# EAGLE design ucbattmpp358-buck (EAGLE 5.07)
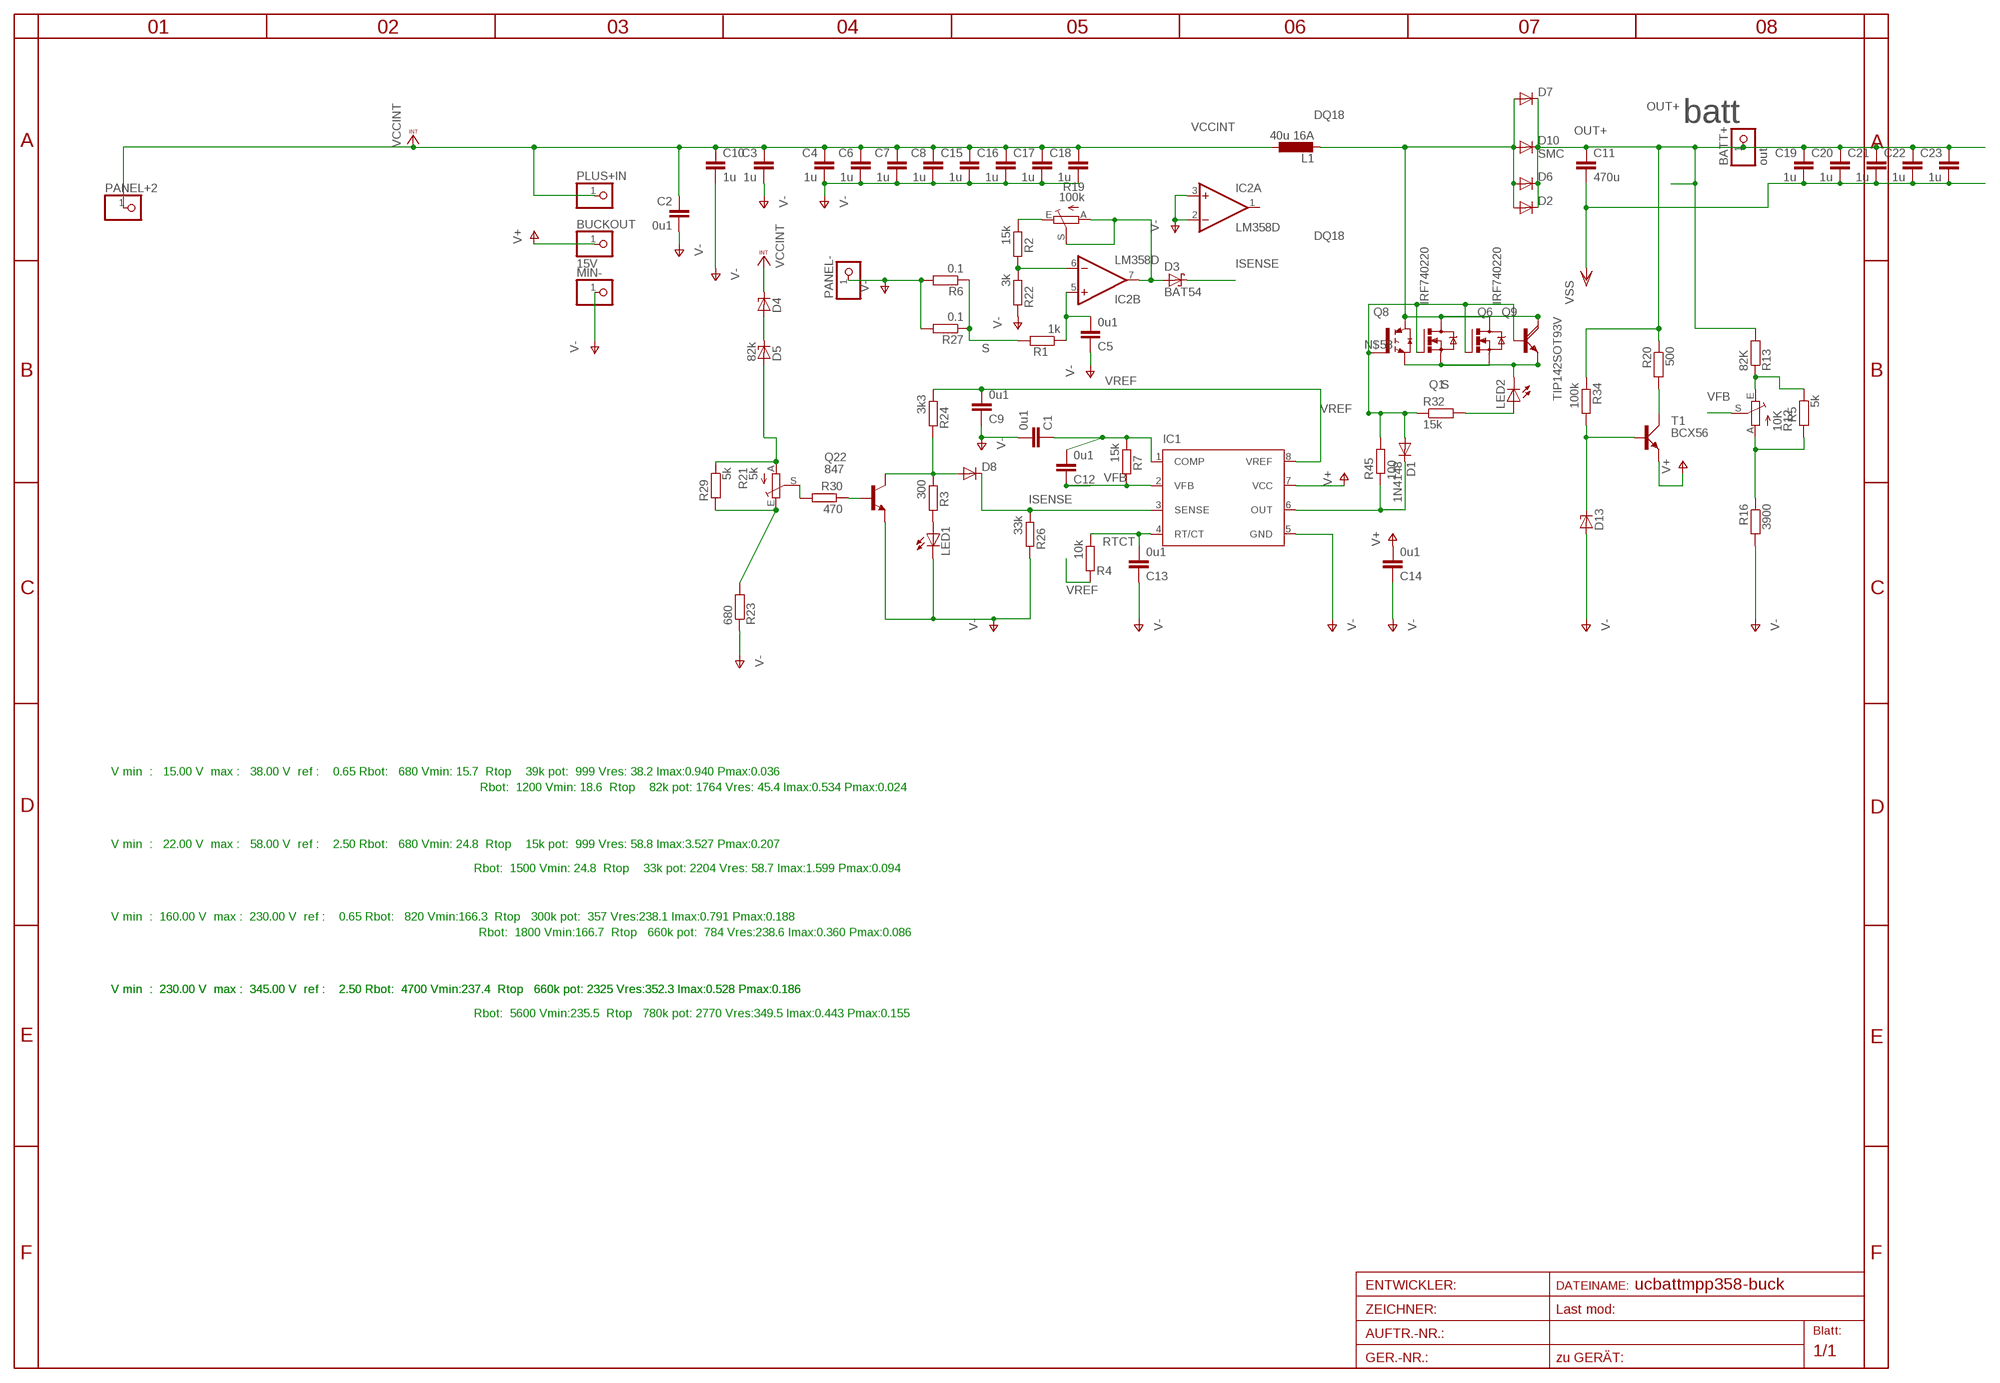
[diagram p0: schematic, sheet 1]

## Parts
BATT+  out  PINHD-1X12MM3  [1X2MM3]
BUCKOUT  15V  PINHD-1X11MM0  [1X1MM0]
C1  0u1  C-EUC1206  [C1206]
C2  0u1  C-EUC1206  [C1206]
C3  1u  C-EUC1206  [C1206]
C4  1u  C-EUC1206  [C1206]
C5  0u1  C-EUC0805  [C0805]
C6  1u  C-EUC1206  [C1206]
C7  1u  C-EUC1206  [C1206]
C8  1u  C-EUC1206  [C1206]
C9  0u1  C-EUC1206  [C1206]
C10  1u  C-EU075-052X106  [C075-052X106]
C11  470u  C-EU075-052X106  [C075-052X106]
C12  0u1  C-EUC0805  [C0805]
C13  0u1  C-EUC1206  [C1206]
C14  0u1  C-EUC1206  [C1206]
C15  1u  C-EUC1206  [C1206]
C16  1u  C-EUC1206  [C1206]
C17  1u  C-EUC1206  [C1206]
C18  1u  C-EUC1206  [C1206]
C19  1u  C-EUC1206  [C1206]
C20  1u  C-EUC1206  [C1206]
C21  1u  C-EUC1206  [C1206]
C22  1u  C-EUC1206  [C1206]
C23  1u  C-EUC1206  [C1206]
D1  1N4148  DIODE-MINIMELF  [MINIMELF]
D2  DIODE-SMC  [SMC]
D3  BAT54  [SOT23]
D4  ZENER-DIODESOD80C  [SOD80C]
D5  82k  ZENER-DIODESOD80C  [SOD80C]
D6  DIODE-SMC  [SMC]
D7  DIODE-SMC  [SMC]
D8  DIODE-MINIMELF  [MINIMELF]
D10  SMC  DIODE-SMC  [SMC]
D13  ZENER-DIODESOD80C  [SOD80C]
IC1  UC1843D8  [SO-08]
IC2  LM358D  [SO08]
L1  40u 16A  L-EU  [RING]
LED1  LEDCHIPLED_1206  [CHIPLED_1206]
LED2  LEDCHIPLED_1206  [CHIPLED_1206]
MIN-  PINHD-1X11MM0  [1X1MM0]
PANEL+2  PINHD-1X12MM3  [1X2MM3]
PANEL-  PINHD-1X12MM3  [1X2MM3]
PLUS+IN  PINHD-1X11MM0  [1X1MM0]
Q1  IRF740220  [TO220BV]
Q6  IRF740220  [TO220BV]
Q8  IRG4BC15UD-S  [D2PACK]
Q9  TIP142SOT93V  [SOT93V]
Q22  847  BC847ASMD  [SOT23]
R1  1k  R-EU_R0805  [R0805]
R2  15k  R-EU_R0805  [R0805]
R3  300  R-EU_R0805  [R0805]
R4  10k  R-EU_R0805  [R0805]
R5  5k  R-EU_R0805  [R0805]
R6  0.1  R-EU_0207/10  [0207/10]
R7  15k  R-EU_R0805  [R0805]
R12  10K  TRIM_EU-S64W  [S64W]
R13  82K  R-EU_R0805  [R0805]
R16  3900  R-EU_R0805  [R0805]
R19  100k  TRIM_EU-S64W  [S64W]
R20  500  R-EU_0204/3  [0204/3]
R21  5k  TRIM_EU-S64W  [S64W]
R22  3k  R-EU_R0805  [R0805]
R23  680  R-EU_R0805  [R0805]
R24  3k3  R-EU_R0805  [R0805]
R26  33k  R-EU_R0805  [R0805]
R27  0.1  R-EU_R3216  [R3216]
R29  5k  R-EU_R0805  [R0805]
R30  470  R-EU_R0805  [R0805]
R32  15k  R-EU_R0805  [R0805]
R34  100k  R-EU_R0805  [R0805]
R45  100  R-EU_R0805  [R0805]
T1  BCX56  [SOT223]

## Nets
DQ18: D2.A D6.A D7.A D10.A L1.2 Q1.D Q6.D Q8.2(C) Q9.C
ISENSE: D3.3(C) D8.C IC1.3(SENSE) R26.1
N$1: C5.2 IC2.5(B:+IN) R1.1
N$2: R2.1 R19.E
N$3: Q22.1(B) R30.1
N$4: LED1.A R3.2
N$5: LED2.A R32.2
N$18: C1.1 C12.2 IC1.1(COMP) R7.1
N$21: R5.2 R12.A R16.1
N$22: D3.1(A) IC2.7(B:OUT) R19.A R19.S
N$23: R20.2 T1.2(C)
N$25: D1.C IC1.6(OUT) R45.1
N$26: D13.C R34.2 T1.1(B)
N$27: IC2.6(B:-IN) R2.2 R22.1
N$30: D4.A D5.C
N$32: D5.A R21.A R29.1
N$34: R21.E R23.2 R29.2
N$37: R5.1 R12.E R13.1
N$58: D1.A Q1.G Q6.G Q8.1(G) Q9.B R32.1 R45.2
N$71: D8.A Q22.3(C) R3.1 R24.2
OUT+: BATT+.1 C11.1 C19.1 C20.1 C21.1 C22.1 C23.1 D2.C D6.C D7.C D10.C R13.2 R20.1 R34.1
PRB1: R21.S R30.2
RTCT: C13.2 IC1.4(RT/CT) R4.1
S: LED2.C Q1.S Q6.S Q8.3(E) Q9.E R1.2 R6.1 R27.1
V+: BUCKOUT.1 C14.2 IC1.7(VCC) T1.3(E)
V-: C1.2 C2.2 C3.2 C4.2 C5.1 C6.2 C7.2 C8.2 C9.1 C10.2 C11.2 C13.1 C14.1 C15.2 C16.2 C17.2 C18.2 C19.2 C20.2 C21.2 C22.2 C23.2 D13.A IC1.5(GND) IC2.2(A:-IN) IC2.3(A:+IN) LED1.C MIN-.1 PANEL-.1 Q22.2(E) R6.2 R16.2 R22.2 R23.1 R26.2 R27.2 ; supply symbol labelled VSS
VCCINT: C2.1 C3.1 C4.1 C6.1 C7.1 C8.1 C10.1 C15.1 C16.1 C17.1 C18.1 D4.C L1.1 PANEL+2.1 PLUS+IN.1
VFB: C12.1 IC1.2(VFB) R7.2 R12.S
VREF: C9.2 IC1.8(VREF) R4.2 R24.1
Unconnected: IC2.1(A:OUT)

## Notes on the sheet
- batt
- V min  :   15.00 V  max :   38.00 V  ref :    0.65 Rbot:   680 Vmin: 15.7  Rtop    39k pot:  999 Vres: 38.2 Imax:0.940 Pmax:0.036
- Rbot:  1200 Vmin: 18.6  Rtop    82k pot: 1764 Vres: 45.4 Imax:0.534 Pmax:0.024
- V min  :   22.00 V  max :   58.00 V  ref :    2.50 Rbot:   680 Vmin: 24.8  Rtop    15k pot:  999 Vres: 58.8 Imax:3.527 Pmax:0.207
- Rbot:  1500 Vmin: 24.8  Rtop    33k pot: 2204 Vres: 58.7 Imax:1.599 Pmax:0.094
- V min  :  160.00 V  max :  230.00 V  ref :    0.65 Rbot:   820 Vmin:166.3  Rtop   300k pot:  357 Vres:238.1 Imax:0.791 Pmax:0.188
- Rbot:  1800 Vmin:166.7  Rtop   660k pot:  784 Vres:238.6 Imax:0.360 Pmax:0.086
- V min  :  230.00 V  max :  345.00 V  ref :    2.50 Rbot:  4700 Vmin:237.4  Rtop   660k pot: 2325 Vres:352.3 Imax:0.528 Pmax:0.186 | V min  :  230.00 V  max :  345.00 V  ref :    2.50 Rbot:  4700 Vmin:237.4  Rtop   660k pot: 2325 Vres:352.3 Imax:0.528 Pmax:0.186
- Rbot:  5600 Vmin:235.5  Rtop   780k pot: 2770 Vres:349.5 Imax:0.443 Pmax:0.155

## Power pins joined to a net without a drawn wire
V+: IC2.8(P:V+)
V-: IC2.4(P:V-)

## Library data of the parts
BATT+ BUCKOUT MIN- PANEL+2 PANEL- PLUS+IN = pinhead:PINHD-1X1: PIN HEADER
C1-C23 = rcl:C-EU: CAPACITOR, European symbol
D1 D2 D6-D8 D10 = diode:DIODE-: DIODE
D3 = diode:BAT54: Schottky Diodes
D4 D5 D13 = diode:ZENER-DIODE: Z-Diode
IC1 = texas:UC1843D8: PULSE WIDTH MODULATOR
IC2 = linear:LM358: OP AMP also LM158; LM258; LM2904 Source: http://cache.national.com/ds/LM/LM158.pdf
L1 = rcl:L-EU: INDUCTOR, European symbol
LED1 LED2 = led:LED: LED
Q1 Q6 = transistor-power:IRF740: N-CHANNEL MOS FET
Q8 = transistor-power:IRG4BC15UD-: INSULATED GATE BIPOLAR TRANSISTOR WITH ULTRAFAST SOFT RECOVERY DIODE
Q9 = transistor-power:TIP142: NPN DARLINGTON TRANSISTOR
Q22 = transistor-npn:BC847*: NPN Transistor
R1-R7 R13 R16 R20 R22-R24 R26 R27 R29 R30 R34 = rcl:R-EU_: RESISTOR, European symbol
R12 R19 R21 = pot:TRIM_EU-: POTENTIOMETER
R32 R45 = rcl-2:R-EU_: RESISTOR, European symbol
T1 = transistor-power:BCX56

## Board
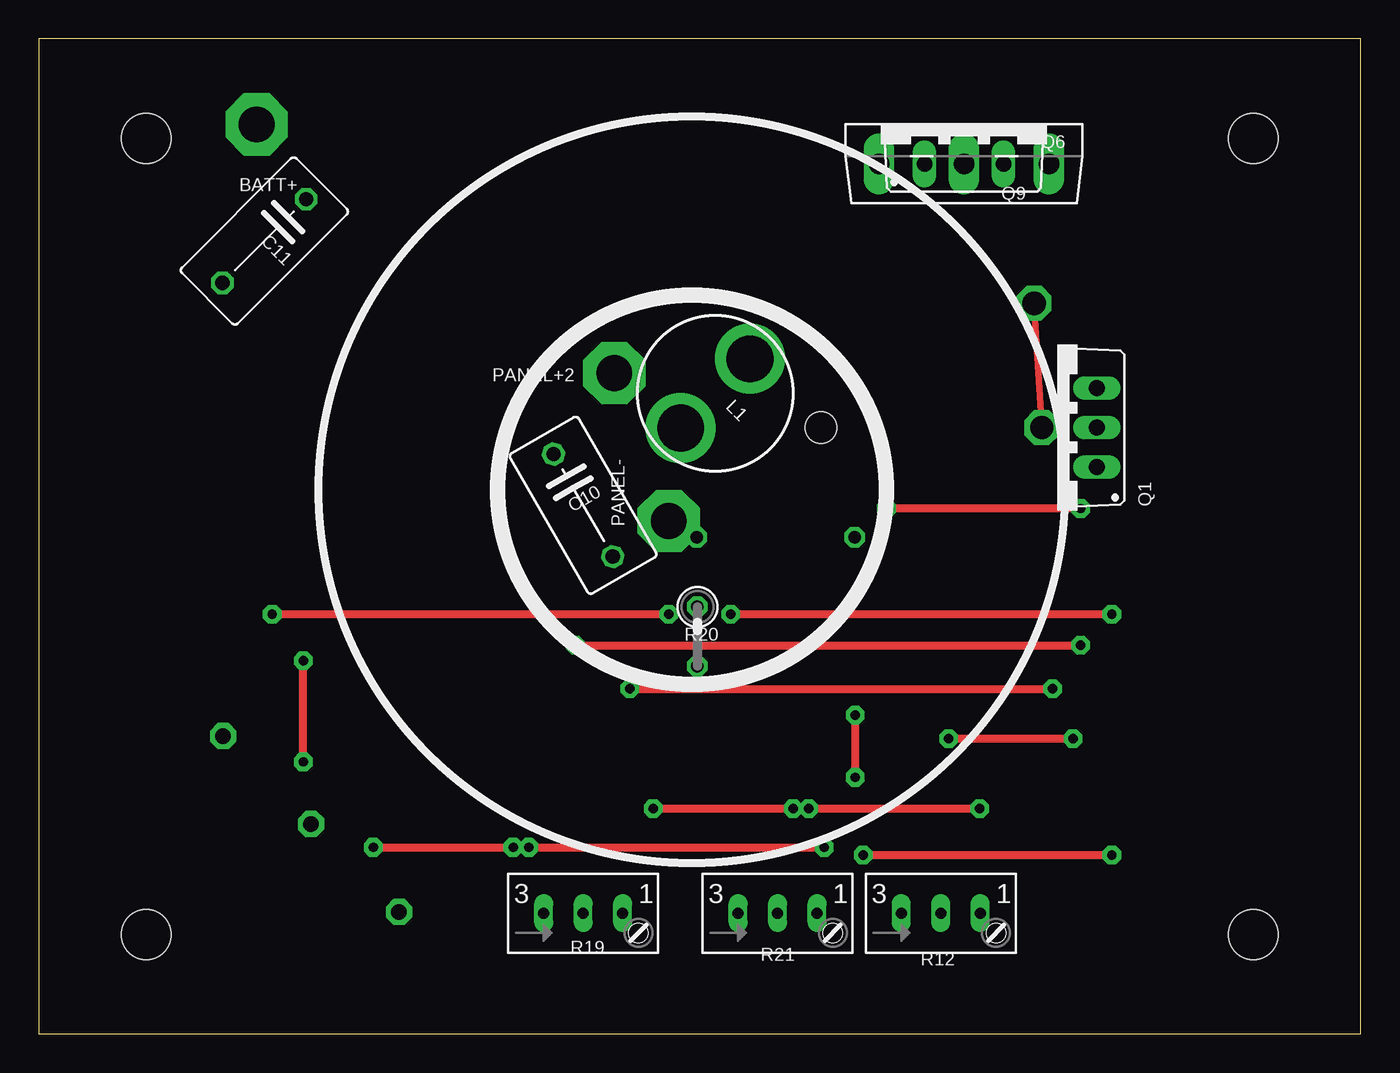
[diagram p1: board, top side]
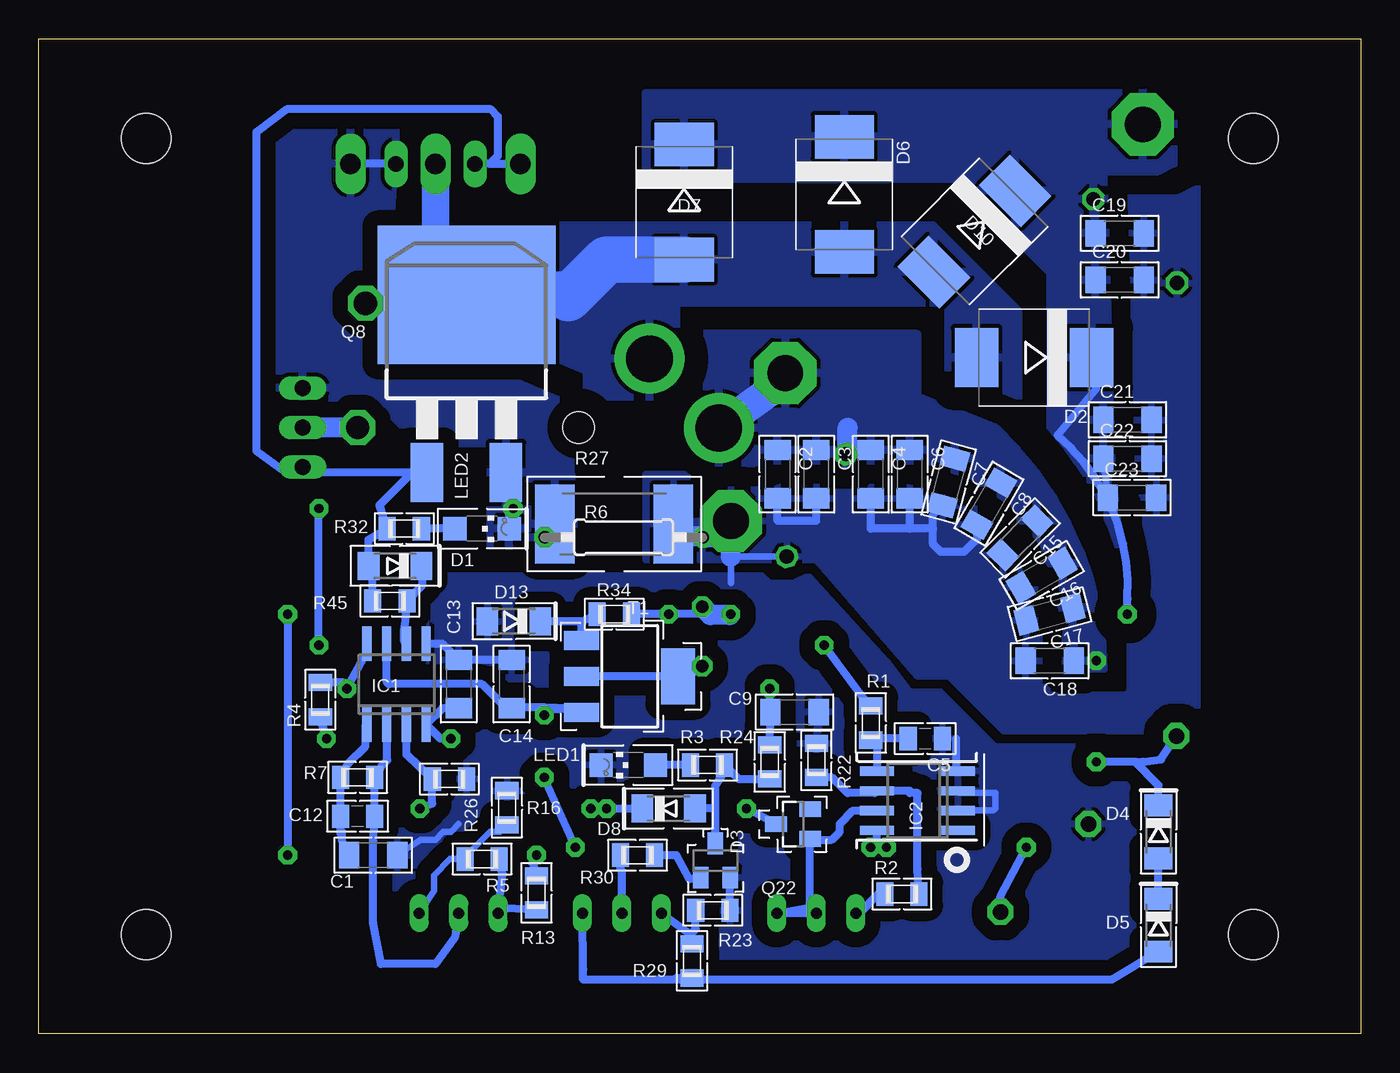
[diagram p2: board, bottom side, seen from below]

Size 85 x 64 mm. Coordinates in mm from the lower left corner, seen from the top.
Outline: 0,0 85,0 85,64 0,64 0,0
Copper layers (1*16): Top 0.035mm / dielectric 1.5mm / Bottom 0.035mm
Design rules "default *": minimum track width 10mil, minimum drill 24mil, track to track 8mil, track to pad 8mil, pad to pad 8mil, via to via 8mil, smd to smd 8mil, copper to edge 1mm, drill to drill 8mil, minimum pad ring 10mil, minimum via ring 8mil, stop-mask expansion 4mil, vias tented up to drill 0mil, thermal gap 10mil
Holes 3.2 mm at 6.9,57.6 6.9,6.4 78.1,6.4 78.1,57.6
Holes 2 mm at 50.3,39

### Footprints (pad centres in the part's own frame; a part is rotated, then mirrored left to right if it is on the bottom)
1X2MM3 = drill 2.3 pad 4 octagon: 1 0,0
1X1MM0 = drill 1 pad 1.676 octagon: 1 0,0
C1206 = smd 1.3 x 1.7: 1 -1.55,0; 2 1.55,0
C0805 = smd 1.1 x 1.5: 1 -1.1,0; 2 1.1,0
C075-052X106 = drill 0.914 octagon: 1 -3.81,0; 2 3.81,0
MINIMELF = smd 1.4 x 1.8: A 1.7,0; C -1.7,0
SMC = smd 2.8 x 3.8: A 3.7,0; C -3.7,0
SOT23 = smd 1 x 1.4: 1 -0.95,-1.1; 2 0.95,-1.1; 3 0,1.1
SOD80C = smd 1.4 x 1.8: A 1.7,0; C -1.7,0
SO-08 = smd 0.6 x 2.2: 1 -1.905,-2.6; 2 -0.635,-2.6; 3 0.635,-2.6; 4 1.905,-2.6; 5 1.905,2.6; 6 0.635,2.6; 7 -0.635,2.6; 8 -1.905,2.6
SO08 = smd 0.6 x 2.2: 1 -1.905,-2.6; 2 -0.635,-2.6; 3 0.635,-2.6; 4 1.905,-2.6; 5 1.905,2.6; 6 0.635,2.6; 7 -0.635,2.6; 8 -1.905,2.6
RING = drill 3 pad 4 round: 1 -3.15,0; 2 3.15,0
CHIPLED_1206 = smd 1.5 x 1.5: A 0,-1.75; C 0,1.75
TO220BV = drill 1.016 long: D 0,-2.54; G -2.54,-2.54; S 2.54,-2.54
D2PACK = smd 2.083 x 3.81: 1 -2.54,-8.89; 3 2.54,-8.89 | smd 11.43 x 8.89: 2 0,2.54
SOT93V = drill 1.3 pad 1.676 long: B -5.461,-2.54; C 0,-2.54; E 5.461,-2.54
R0805 = smd 1.1 x 1.5: 1 -1.1,0; 2 1.1,0
0207/10 = drill 0.813 octagon: 1 -5.08,0; 2 5.08,0
S64W = drill 0.7 long: A 2.54,1.27; E -2.54,1.27; S 0,1.27
0204/3 = drill 0.813 octagon: 1 -1.27,0; 2 2.54,0
R3216 = smd 2.54 x 5.08: 1 -3.81,0; 2 3.81,0
SOT223 = smd 1.219 x 2.235: 1 -2.311,-3.099; 2 0,-3.099; 3 2.311,-3.099 | smd 3.6 x 2.2: 4 0,3.099

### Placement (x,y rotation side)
BATT+  14,58.5 0 top
BUCKOUT  23.16,7.84 90 top
C1  63.5,11.5 0 bottom
C2  37.5,36 270 bottom
C3  35,36 270 bottom
C4  31.5,36 270 bottom
C5  28,19 180 bottom
C6  29,36 270 bottom
C7  26.5,35.5 255 bottom
C8  23.9,34.1 240 bottom
C9  36.4,20.7 180 bottom
C10  35,34 300 top
C11  14.5,51 225 top
C12  64.5,14 180 bottom
C13  58,22.5 270 bottom
C14  54.6,22.5 270 bottom
C15  21.9,31.9 225 bottom
C16  20.5,29.5 210 bottom
C17  20,27 195 bottom
C18  20,24 180 bottom
C19  15.5,51.5 0 bottom
C20  15.5,48.5 0 bottom
C21  15,39.5 0 bottom
C22  15,37 0 bottom
C23  14.7,34.5 0 bottom
D1  62.1,30.1 180 bottom
D2  21,43.5 180 bottom
D3  36.5,13.5 90 bottom
D4  13,13 270 bottom
D5  13,7 270 bottom
D6  33.2,54 270 bottom
D7  43.5,53.5 270 bottom
D8  44.5,14.5 0 bottom
D10  24.83,51.61 225 bottom
D13  54.46,26.55 180 bottom
IC1  62,22.5 0 bottom
IC2  28.5,15 90 bottom
L1  43.5,41.2 45 top
LED1  47.1,17.3 90 bottom
LED2  56.5,32.5 270 bottom
MIN-  17.5,13.5 315.7 top
PANEL+2  37,42.5 0 top
PANEL-  40.5,33 90 top
PLUS+IN  11.84,19.16 90 top
Q1  65.5,39 90 top
Q6  59.5,58.5 0 top
Q8  57.5,45 0 bottom
Q9  59.5,58.5 0 top
Q22  41.49,11.16 0 bottom
R1  31.5,20 90 bottom
R2  29.5,9 0 bottom
R3  42,17.3 180 bottom
R4  66.9,21.5 90 bottom
R5  56.5,11.25 180 bottom
R6  47.4,31.95 0 bottom
R7  64.5,16.5 0 bottom
R12  58,6.5 0 top
R13  53,9.08 90 bottom
R16  54.9,14.55 90 bottom
R19  35,6.5 0 top
R20  42.35,26.2 270 top
R21  47.5,6.5 0 top
R22  35,17.6 90 bottom
R23  41.66,7.96 180 bottom
R24  38,17.5 270 bottom
R26  58.6,16.4 0 bottom
R27  48,32.8 0 bottom
R29  43,4.7 90 bottom
R30  46.5,11.5 180 bottom
R32  61.5,32.5 0 bottom
R34  48,27 180 bottom
R45  62.43,27.85 180 bottom
T1  47,23 270 bottom

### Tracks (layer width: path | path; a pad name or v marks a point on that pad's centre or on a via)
DQ18  (via drill 1.5 pad 1.6, 1.5 pad 1.78)
  Top 0.406: v64,47 v64.5,39
  Bottom 0.406: v64,47 58.9,47 58.9,47.89
  Bottom 1.27: v64.5,39 Q1.D
  Bottom 1.778: 59.5,48.04 Q9.C
  Bottom 2.54: Q8.2 58.9,47.89 59.5,48.04
  Bottom 3: Q8.2 51.04,47.54 50.97,47.34 48.51,49.8 D7.A
  pour Bottom (isolate 1.5, rank 2): 27.5,52 53,52 52,43 49.5,41 44.5,41 44.5,45.5 27.5,45.5 27.5,40.5 22,40.5 22,46.5
ISENSE  (via drill 0.6 pad 1.2)
  Top 0.5: v49.5,14.5 v60.5,14.5 | v39.5,14.5 v48.5,14.5
  Bottom 0.5: IC1.3 61.37,17.96 R26.1 59.7,14.8 v60.5,14.5 | v49.5,14.5 v48.5,14.5 D8.C | D3.3 v39.5,14.5
N$1
  Bottom 0.5: IC2.5 31.1,18.5 R1.1 31.5,19 C5.2
N$2
  Bottom 0.5: R2.1 31,9 32.23,7.77 R19.E
N$3
  Bottom 0.5: Q22.1 43.16,9.96 44,11.5 R30.1
N$4
  Bottom 0.5: R3.2 LED1.A
N$5
  Bottom 0.5: LED2.A R32.2
N$18
  Bottom 0.5: C1.1 65.5,12.45 65.5,13 65.6,12.9 C12.2 R7.1 65.1,17.4 64,18.5 64,19.8 IC1.1
N$21
  Bottom 0.406: R16.1 55.35,13 56,13 57.6,11.4 R5.2 58.55,11.25 59.6,10.2 59.6,9.22 R12.A
N$22
  Bottom 0.5: IC2.7 32.63,14.37 33.5,13.5 33.5,13 34,12.5 35.35,12.5 D3.1 35.4,8.13 R19.A R19.S
N$23
  Bottom 0.5: R20.2 43.19,23 43.5,22 44,22.5 44,23 T1.2
N$25
  Bottom 0.5: IC1.6 61.5,25.23 61.5,26 61.43,26.57 R45.1 60.33,28.87 D1.C
N$26
  Bottom 0.5: R34.2 50.21,26.5 49.99,26.52 | 49.99,26.52 D13.C | T1.1 50.1,26.42 49.99,26.52
N$27
  Bottom 0.5: R2.2 28.5,10.6 28.5,15.5 29,15.5 29,15.63 IC2.6 31.23,15.5 33,15.5 34,16.5 R22.1
N$30
  Bottom 0.5: D5.C D4.A
N$32
  Bottom 0.5: D5.A 16,3.5 44,3.5 | 44,3.5 50,3.5 50,4.14 R21.A | R29.1 44,3.6 44,3.5
N$34
  Bottom 0.5: R29.2 43,6.3 43.1,6.4 | 43.1,6.4 R21.E | R23.2 42.76,6.74 43.1,6.4
N$37
  Bottom 0.5: R13.1 55.03,8.07 R12.E 55.16,10.27 R5.1
N$58
  Bottom 0.406: Q1.G 68.5,36.46 68.5,36.11
  Bottom 0.5: 56,55.96 Q9.B | 56,55.96 Q6.G | R45.2 63.53,29.43 D1.A 63.8,31.8 R32.1 63.1,34.01 61,36.11 | 61,36.11 Q8.1 | 61,36.11 68.5,36.11 69.11,36.11 71,37.5 71,58 69,59.5 56,59.5 55.5,59 55.5,56.46 56,55.96
N$71
  Bottom 0.5: Q22.3 41.49,14.5 | 41.49,14.5 41.49,15.96 40.9,16.87 R3.1 40,16.4 R24.2 | 41.49,14.5 D8.A
OUT+  (via drill 0.6 pad 1.2)
  Top 0.5: v69,11.5 v53,11.5 | v15,27 v40.5,27 | v44.5,27 v69,27
  Bottom 0.406: C23.1 C22.1
  Bottom 0.5: v69,27 v69,11.5 | v53,11.5 53.26,11 R13.2 | v15,27 15,28 arc-53 19.5,38.5 17,41.5 17,43.7 D2.C | v40.5,27 40.56,26.94 | R20.1 42,26.99 42,27 v44.5,27 R34.1
  Bottom 1.27: 40.56,26.94 41.82,26.94 R20.1
  pour Bottom (isolate 1.5, rank 3): 12,56 12,60.5 46,60.5 46,55 26,55 20,49 20,38.5 arc46 16,31.5 15.5,31.5 16,36.5 16.5,55.5 13,55.5
PRB1
  Bottom 0.5: R30.2 47.6,10.6 47.5,10.5 R21.S
RTCT  (via drill 0.6 pad 1.2)
  Top 0.5: v58.5,19 v66.5,19
  Bottom 0.5: C13.2 59.05,20.95 IC1.4 59.2,19 v58.5,19 | v66.5,19 R4.1
S  (via drill 0.6 pad 1.2)
  Top 0.5: v67,33.8 v54.5,33.8 | v34.5,25 v67,25
  Bottom 0.5: Q6.S Q9.E | Q8.3 54.61,36.11 | LED2.C 54.75,33.75 v54.5,33.8 54.5,34.5 | v67,25 v67,33.8 | v34.5,25 32,21.6 R1.2
  Bottom 1.27: R6.1 51.81,31.95 R27.1
  pour Bottom (isolate 1): 62,58 70.5,58 71,57.5 71,39 69.5,39 68.5,40 62.5,40 60.5,38 56,38 56,31.5 50.5,31 51,40.5 54.5,42 62.5,42 63,42.5
V+  (via drill 0.6 pad 1.2)
  Top 0.5: v31.5,12 v50.5,12 | v52.5,16.5 v52.5,20.5 | v21.5,12 v30.5,12
  Bottom 0.5: IC2.8 31.1,12.1 v31.5,12 v30.5,12 | v50.5,12 v52.5,16.5 | IC1.7 62.63,22.64 62.5,22.5 56.5,22.5 55,21 | 55,21 52.41,21 50.94,20.94 | 50.94,20.94 T1.3 | v52.5,20.5 52,20.88 50.94,20.94 | BUCKOUT.1 23.16,8.84 v21.5,12 | C14.2 55.05,21 55,21
V-
  Bottom 0.406: C1.2 60.45,12.5 59.5,12.5 59,13 58.5,13 58,13.5 | C10.2 40.5,30.7 40.5,29 | IC2.2 23.64,14.37 23.5,14.5 23.5,15.5 25.77,15.5 IC2.3
  Bottom 0.5: C14.1 C13.1 59.05,25.1 IC1.5 | R23.1 40.5,8 40.5,7.5 40.54,8.47 Q22.2 | IC2.4 26,17 26,19 | C8.2 24.68,31.82 25.5,31 27,31 27.5,31.5 27.5,32.5 | 27.5,32.5 27.5,33.4 C7.2 | 29,32.5 C6.2 | 27.5,32.5 29,32.5 | C4.2 31.5,32.5 29,32.5 | C2.2 37.5,33 35,33 C3.2
  Bottom 1.27: 40.5,32 PANEL-.1 | 40.5,30.7 40.5,32 | 40.5,32 41,32 | 41,32 44.19,32 R27.2 | R6.2 41.5,31.95 41,32
  pour Bottom (isolate 1.25, rank 4): 28.5,23 26.5,23 23,19.5 12.5,19.5 10.5,21 10.5,54.5 17,54.5 16.5,23.5 20,23.5 arc-61 26.5,36 46,36 46,30.5 35,30.5
  pour Bottom (isolate 1): 35.5,29.5 36.5,29 38,29 38.5,29.5 70,29.5 70,4 12,4 12,18.5 23.5,18.5 27,22 29,22 30.5,24
VCCINT  (via drill 0.6 pad 1.2)
  Top 0.5: v17,17.5 v17,24
  Bottom 0.5: PLUS+IN.1 12.84,17.66 14,17.5 14.5,17.5 | 14.5,17.5 v17,17.5 | D4.C 13,16 14.5,17.5
  Bottom 1.27: C10.1 33,37.3 33,39
  Bottom 2: 37,42.05 L1.1
  Bottom 3: PANEL+2.1 37,42.05
  pour Bottom (isolate 1.5): 28.5,45 42.5,45 42.5,36 27.5,35.5 arc83 19,23.5 16.5,23.5 arc-46 23.5,39 28.5,41
VFB
  Bottom 0.5: R12.S 58.2,6.29 59.5,4.5 63,4.5 63.5,7.13 63.5,12.4 63.4,13.66 C12.1 R7.2 62.9,17.3 62.6,17.6 62.6,19.86 IC1.2
VREF  (via drill 0.6 pad 1.2)
  Top 0.5: v38,22.2 v65.2,22.2
  Bottom 0.5: R24.1 C9.2 38,21.95 v38,22.2 | IC1.8 63.91,24.59 v65.2,22.2 65.4,22.6 R4.2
